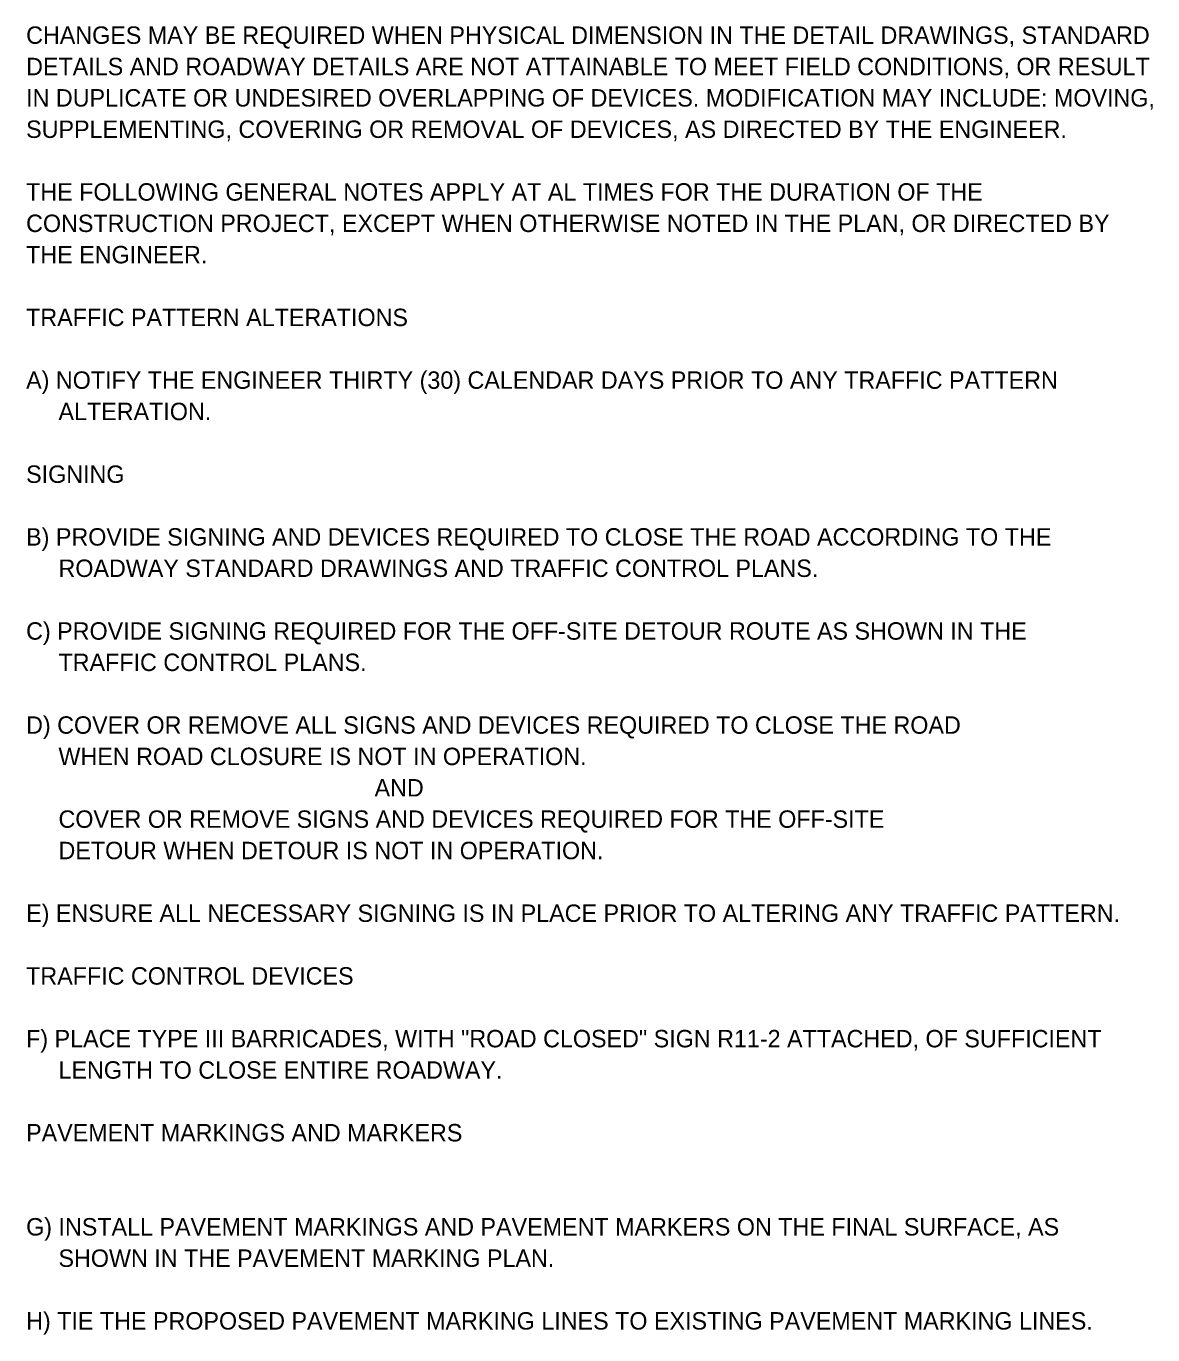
# Model space of a CAD drawing. Extents: x -38542 to 45858, y -25814 to 29186.
# Drawn here: x 2636 to 3090, y -295 to 232 of the extents above; entities that cross this region are included whole.
import ezdxf

# ---------------------------------------------------------------- set-up
doc = ezdxf.new("R2010")
doc.units = 0
doc.layers.add('DEV TYPE 3 BARRICADE WITH R11-2 M4-10R CELL', color=7, linetype='Continuous')

msp = doc.modelspace()

# ---------------------------------------------------------------- texts
at = {"layer": 'DEV TYPE 3 BARRICADE WITH R11-2 M4-10R CELL'}
for s, p in [('CHANGES MAY BE REQUIRED WHEN PHYSICAL DIMENSION IN THE DETAIL DRAWINGS, STANDARD', (2636.23, 224.84)), ('DETAILS AND ROADWAY DETAILS ARE NOT ATTAINABLE TO MEET FIELD CONDITIONS, OR RESULT ', (2636.23, 212.2)), ('IN DUPLICATE OR UNDESIRED OVERLAPPING OF DEVICES. MODIFICATION MAY INCLUDE: MOVING,', (2636.23, 199.57)), ('SUPPLEMENTING, COVERING OR REMOVAL OF DEVICES, AS DIRECTED BY THE ENGINEER. ', (2636.23, 186.93)), ('THE FOLLOWING GENERAL NOTES APPLY AT AL TIMES FOR THE DURATION OF THE ', (2636.23, 161.66)), ('CONSTRUCTION PROJECT, EXCEPT WHEN OTHERWISE NOTED IN THE PLAN, OR DIRECTED BY ', (2636.23, 149.02)), ('THE ENGINEER.', (2636.23, 136.39)), ('TRAFFIC PATTERN ALTERATIONS', (2636.23, 111.11)), ('A) NOTIFY THE ENGINEER THIRTY (30) CALENDAR DAYS PRIOR TO ANY TRAFFIC PATTERN ', (2636.23, 85.84)), ('     ALTERATION.', (2636.23, 73.21)), ('SIGNING', (2636.23, 47.93)), ('B) PROVIDE SIGNING AND DEVICES REQUIRED TO CLOSE THE ROAD ACCORDING TO THE ', (2636.23, 22.66)), ('     ROADWAY STANDARD DRAWINGS AND TRAFFIC CONTROL PLANS.', (2636.23, 10.03)), ('C) PROVIDE SIGNING REQUIRED FOR THE OFF-SITE DETOUR ROUTE AS SHOWN IN THE ', (2636.23, -15.25)), ('     TRAFFIC CONTROL PLANS. ', (2636.23, -27.88)), ('D) COVER OR REMOVE ALL SIGNS AND DEVICES REQUIRED TO CLOSE THE ROAD', (2636.23, -53.15)), ('     WHEN ROAD CLOSURE IS NOT IN OPERATION.', (2636.23, -65.79)), ('AND', (2776.63, -78.43)), ('     COVER OR REMOVE SIGNS AND DEVICES REQUIRED FOR THE OFF-SITE ', (2636.23, -91.06)), ('     DETOUR WHEN DETOUR IS NOT IN OPERATION.', (2636.23, -103.7)), ('E) ENSURE ALL NECESSARY SIGNING IS IN PLACE PRIOR TO ALTERING ANY TRAFFIC PATTERN.', (2636.23, -128.97)), ('TRAFFIC CONTROL DEVICES', (2636.23, -154.24)), ('F) PLACE TYPE III BARRICADES, WITH "ROAD CLOSED" SIGN R11-2 ATTACHED, OF SUFFICIENT', (2636.23, -179.51)), ('     LENGTH TO CLOSE ENTIRE ROADWAY.', (2636.23, -192.15)), ('PAVEMENT MARKINGS AND MARKERS', (2636.23, -217.42)), ('G) INSTALL PAVEMENT MARKINGS AND PAVEMENT MARKERS ON THE FINAL SURFACE, AS ', (2636.23, -255.33)), ('     SHOWN IN THE PAVEMENT MARKING PLAN.', (2636.23, -267.97)), ('H) TIE THE PROPOSED PAVEMENT MARKING LINES TO EXISTING PAVEMENT MARKING LINES.', (2636.23, -293.24))]:
    msp.add_text(s, height=7.02, dxfattribs=at).set_placement(p)

doc.saveas('drawing.dxf')
